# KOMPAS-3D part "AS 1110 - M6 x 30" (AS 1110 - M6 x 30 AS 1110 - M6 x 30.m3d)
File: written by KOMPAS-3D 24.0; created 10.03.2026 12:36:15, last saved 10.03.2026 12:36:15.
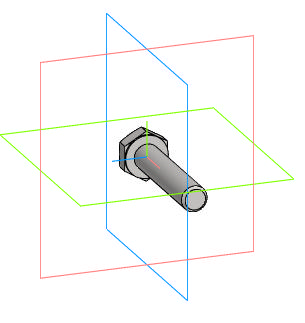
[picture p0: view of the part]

Document properties: Автор: R2D2; Полное имя файла: E:\Работа\Зайцев\BV3232P(4pc)-FP-3WL-F-ISO-H Кран шаровой DN.ru Ду15-100 Ру16\DN40\исходные материалы\AS 1110 - M6 x 30 AS 1110 - M6 x 30.m3d

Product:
- Body: Solid1  | qty 1
- Part/product: AS 1110 - M6 x 30
    Комментарий: Болты и винты   шестигранные точные   метрические ISO
    additional columns: Сталь, мягкая

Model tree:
1. Solid1  (labels: Solid1)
